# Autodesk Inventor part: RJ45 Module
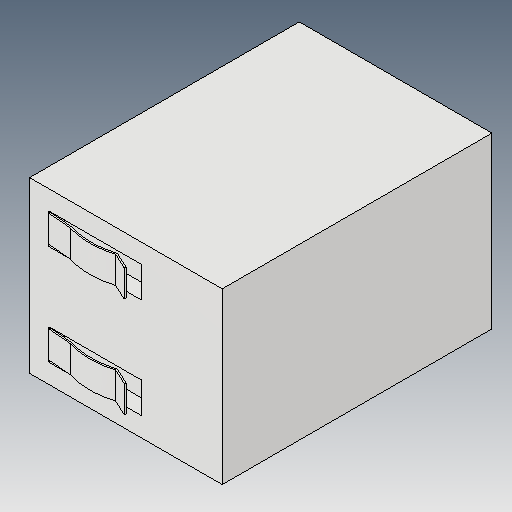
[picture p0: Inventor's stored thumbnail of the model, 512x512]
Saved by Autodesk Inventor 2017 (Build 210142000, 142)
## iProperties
Created: 2005-11
Part Number: RJ45 Module
Material: Generic
Document SubType Name: Modeling
Designer: DanielSeverino
Density: 1 g/cm^3
Appearance: Default
Author: DanielSeverino
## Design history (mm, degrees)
feature "Solid1"
body "Solid2"
